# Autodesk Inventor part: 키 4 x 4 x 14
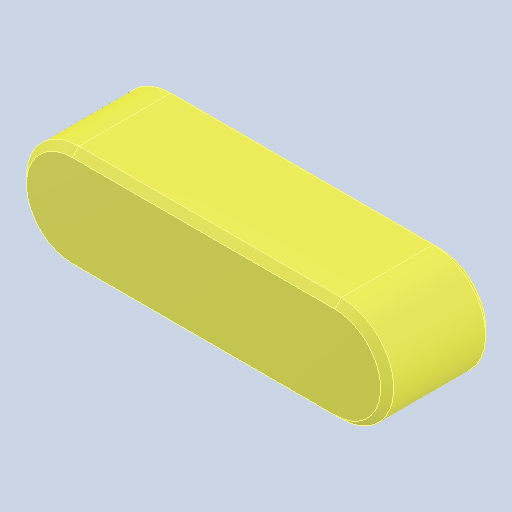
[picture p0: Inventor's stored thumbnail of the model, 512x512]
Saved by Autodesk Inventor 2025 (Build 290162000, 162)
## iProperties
Created: 2024-07
Part Number: 키 4 x 4 x 14
Material: 강철, 연강
Description: 키 및 해당 키홈
Document SubType Name: Modeling
Designer: 학생
Density: 7.85 g/cm^3
Appearance: 기본값
Author: jhkim
Sending System: Autodesk Inventor 2025
Preprocessor: ST-DEVELOPER v20
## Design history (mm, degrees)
feature "Solid1"
node "솔리드1"
